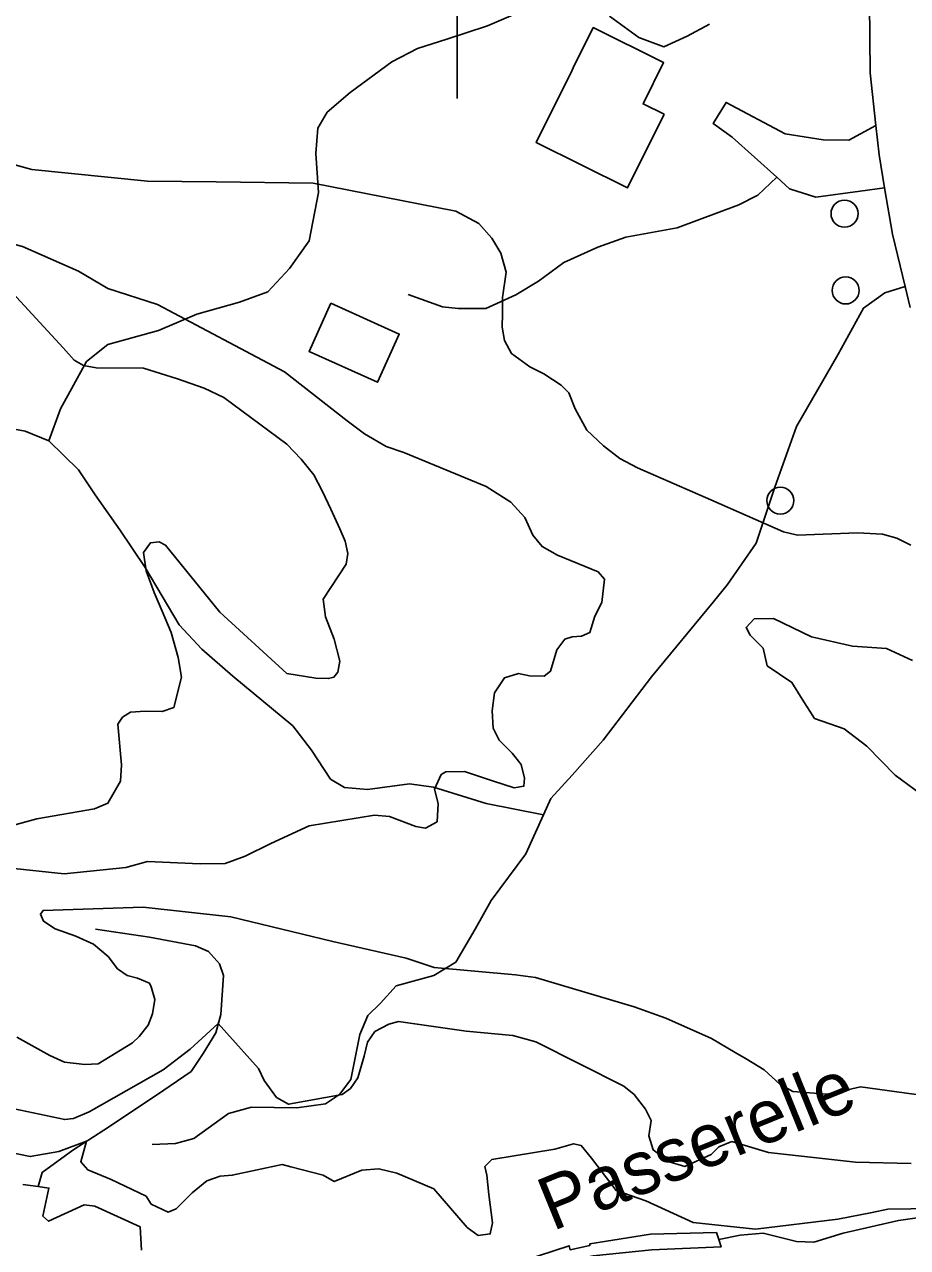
# Model space of a CAD drawing. Extents: x 362852 to 366875, y 5563573 to 5566479.
# Drawn here: x 363568 to 363633.3, y 5564105 to 5564195.5 of the extents above; entities that cross this region are included whole.
import ezdxf

# ---------------------------------------------------------------- set-up
doc = ezdxf.new("R2010")
doc.units = 0
for name, color, linetype in [('Niveau 1', 7, 'Continuous'), ('Niveau 19', 7, 'Continuous'), ('Niveau 2', 7, 'Continuous'), ('Niveau 21', 7, 'Continuous'), ('Niveau 22', 7, 'Continuous'), ('Niveau 26', 7, 'Continuous'), ('Niveau 31', 7, 'Continuous'), ('Niveau 36', 7, 'Continuous'), ('Niveau 4', 7, 'Continuous'), ('Niveau 61', 7, 'Continuous')]:
    doc.layers.add(name, color=color, linetype=linetype)

msp = doc.modelspace()

# ---------------------------------------------------------------- linework, layer by layer
at = {"layer": 'Niveau 1'}
msp.add_lwpolyline([(363566.31, 5564176.54), (363570.89, 5564171.56), (363571.71, 5564170.65), (363572.38, 5564170.25), (363573.32, 5564170.08), (363576.82, 5564170.06), (363579.34, 5564169.25), (363581.3, 5564168.58), (363582.77, 5564167.89), (363587.41, 5564164.42), (363588.49, 5564163.31), (363589.42, 5564162.15), (363590.06, 5564160.92), (363590.67, 5564159.62), (363591.34, 5564158.16), (363591.72, 5564157.26), (363591.92, 5564156.34), (363591.81, 5564155.55), (363590.1, 5564152.96), (363590.27, 5564151.66), (363590.91, 5564150), (363591.34, 5564148.38), (363591.18, 5564147.56), (363590.9, 5564147.19), (363590.51, 5564147.09), (363589.56, 5564147.13), (363587.42, 5564147.48), (363582.47, 5564152), (363578.45, 5564156.97), (363577.98, 5564157.21), (363577.33, 5564157.13), (363576.82, 5564156.41), (363577.01, 5564155.06), (363577.62, 5564153.45), (363578.2, 5564152.07), (363578.87, 5564150.49), (363579.39, 5564148.65), (363579.63, 5564147.19), (363579.07, 5564144.96), (363578.2, 5564144.66), (363576.94, 5564144.69), (363575.86, 5564144.61), (363575.27, 5564144.24), (363574.92, 5564143.72), (363575.19, 5564140.71), (363575.13, 5564139.51), (363574.2, 5564137.87), (363573.2, 5564137.45), (363568.95, 5564136.72), (363566.88, 5564136.16)], dxfattribs=at)
at = {"layer": 'Niveau 19'}
msp.add_lwpolyline([(363631.6, 5564183.39), (363629.8, 5564183.13), (363626.53, 5564182.7), (363624.58, 5564183.32), (363623.64, 5564184.17), (363620.33, 5564187.13), (363618.94, 5564188.14), (363619.88, 5564189.7), (363624.26, 5564187.38), (363627.07, 5564186.93), (363628.96, 5564186.91), (363630.96, 5564187.99)], dxfattribs=at)
at = {"layer": 'Niveau 2'}
for points in [[(363536.07, 5564212.57), (363538.28, 5564211.63), (363539.95, 5564210.64), (363541.47, 5564209.4), (363545.42, 5564205.94), (363548.14, 5564203.33), (363549.77, 5564201.39), (363551.22, 5564199.44), (363552.37, 5564197.73), (363553.17, 5564196.26), (363557.49, 5564188.95), (363559.34, 5564187.23), (363560.39, 5564186.98), (363561.65, 5564186.63), (363568.58, 5564184.73), (363577.12, 5564183.88), (363582.2, 5564183.83), (363589.37, 5564183.72), (363599.92, 5564181.66), (363601.62, 5564180.74), (363602.58, 5564179.65), (363603.23, 5564178.55), (363603.63, 5564177.15)], [(363524.9, 5564201.47), (363536.51, 5564194.18), (363547.07, 5564189.26), (363557.67, 5564183.92), (363560.63, 5564181.61), (363562.21, 5564180.83), (363563.68, 5564180.14), (363564.32, 5564179.97), (363567.89, 5564179.04), (363570.8, 5564177.77), (363572.02, 5564177.22), (363574.18, 5564175.94), (363577.86, 5564174.75), (363587.25, 5564169.77)], [(363603.63, 5564177.15), (363603.35, 5564175.28), (363603.35, 5564174.1), (363603.33, 5564173.09), (363603.5, 5564172.1), (363604.03, 5564171.13), (363605.38, 5564170.14), (363606.41, 5564169.63), (363607.7, 5564168.8), (363608.25, 5564168.22), (363608.74, 5564167.05), (363609.59, 5564165.47), (363610.83, 5564164.3), (363612.04, 5564163.37), (363613.33, 5564162.67), (363618.75, 5564160.32), (363624.12, 5564157.95), (363625.16, 5564157.7), (363629.59, 5564157.88), (363631.44, 5564157.78), (363632.51, 5564157.48), (363633.53, 5564156.97)], [(363587.25, 5564169.77), (363591.89, 5564166.16), (363593.16, 5564165.2), (363594.75, 5564164.25), (363596.06, 5564163.8), (363602.16, 5564161.31), (363603.97, 5564160.13), (363605, 5564159.01), (363605.61, 5564157.7), (363606.28, 5564156.86), (363607.42, 5564156.22), (363610.43, 5564154.99), (363610.91, 5564154.44), (363610.69, 5564152.73), (363610.19, 5564151.7), (363609.82, 5564150.49), (363609.19, 5564150.22), (363608.52, 5564150.19), (363607.96, 5564150.02), (363607.37, 5564149.21), (363606.9, 5564147.64), (363606.44, 5564147.26), (363605.36, 5564147.3), (363604.55, 5564147.46), (363603.5, 5564147.14), (363602.78, 5564146.03), (363602.59, 5564144.7), (363602.68, 5564143.43), (363603.12, 5564142.55), (363604.08, 5564141.59), (363604.75, 5564140.74), (363604.99, 5564139.72), (363604.93, 5564139.13), (363604.22, 5564139.02), (363602.63, 5564139.54), (363600.54, 5564140.22), (363599.17, 5564140.21), (363598.82, 5564140), (363598.34, 5564138.92), (363598.6, 5564137.85), (363598.54, 5564136.51), (363597.68, 5564136.03), (363596.95, 5564136.15), (363595.01, 5564136.9), (363593.91, 5564137), (363589.06, 5564136.21), (363586.24, 5564134.9), (363584.33, 5564133.97), (363582.87, 5564133.42), (363581.01, 5564133.39), (363577.13, 5564133.56), (363575.51, 5564133.13), (363570.96, 5564132.66), (363566.79, 5564133.09)], [(363634.26, 5564138.58), (363632.37, 5564139.96), (363630.29, 5564142.09), (363628.62, 5564143.38), (363626.43, 5564144.15), (363625.52, 5564145.57), (363624.75, 5564146.81), (363622.92, 5564148.04), (363622.62, 5564149.35), (363621.66, 5564150.31), (363621.36, 5564150.88), (363621.97, 5564151.51), (363623.39, 5564151.54), (363626.21, 5564150.17), (363629.23, 5564149.5), (363631.75, 5564149.31), (363633.67, 5564148.44)], [(363635.18, 5564116.16), (363629.81, 5564116.9), (363628.55, 5564116.62), (363627.34, 5564116.37), (363624.83, 5564116.56), (363623.85, 5564117.09), (363622.71, 5564118.17), (363621.37, 5564118.98), (363620.55, 5564119.45), (363618.81, 5564120.47), (363615.43, 5564121.98), (363613.08, 5564122.81), (363605.79, 5564124.99), (363604.33, 5564125.19), (363598.3, 5564125.72), (363596.25, 5564126.42), (363590.81, 5564127.64), (363583.29, 5564129.47), (363576.8, 5564130.19), (363569.4, 5564129.95), (363569.21, 5564129.68), (363569.43, 5564129.15), (363570.29, 5564128.58), (363571.83, 5564128.04), (363573.14, 5564127.46), (363574.21, 5564126.54), (363574.9, 5564125.64), (363575.62, 5564125.13), (363576.38, 5564124.95), (363577.28, 5564124.58)], [(363580.27, 5564119.69), (363578.28, 5564118.17), (363572.82, 5564115.06), (363571.65, 5564114.57), (363571, 5564114.48), (363566.33, 5564115.47), (363562.24, 5564117.31), (363561.74, 5564117.92), (363560.98, 5564118.97), (363560.19, 5564119.52), (363558.96, 5564120.06), (363557.14, 5564120.37), (363551.49, 5564120.12), (363550.1, 5564119.85), (363548.81, 5564119.93), (363547.81, 5564120.39), (363546.88, 5564121.25), (363543.51, 5564124.65)], [(363577.28, 5564124.58), (363577.4, 5564124.31), (363577.67, 5564123.36), (363577.5, 5564122.29), (363577.16, 5564121.46), (363576.51, 5564120.62), (363576.01, 5564120.17), (363573.48, 5564118.6), (363572.5, 5564118.56), (363570.99, 5564118.74), (363569.91, 5564119.23), (363567.47, 5564120.58)], [(363600.68, 5564121.01), (363595.68, 5564121.73), (363594.95, 5564121.54), (363593.93, 5564120.99), (363593.38, 5564120.2), (363593.13, 5564119.16), (363592.67, 5564117.58), (363592.13, 5564116.79), (363591.5, 5564116.34), (363587.55, 5564115.62), (363586.65, 5564116.12), (363585.75, 5564117.37), (363585.32, 5564118.25), (363582.35, 5564121.58), (363580.27, 5564119.69)], [(363633.57, 5564111.24), (363629.46, 5564111.33), (363623.02, 5564112.06), (363620.31, 5564112.86), (363619.35, 5564112.46), (363618.77, 5564111.9), (363616.83, 5564111.02), (363615.68, 5564111.36), (363614.5, 5564112.24), (363614.18, 5564113.29), (363614.34, 5564114.42), (363613.92, 5564115.25), (363613.09, 5564116.34), (363612.33, 5564116.96), (363605.82, 5564120.23), (363604.12, 5564120.71), (363600.68, 5564121.01)], [(363565.44, 5564112.36), (363568.46, 5564111.74), (363570.56, 5564112.12), (363572.62, 5564112.88), (363572.19, 5564111.37), (363572.7, 5564110.77), (363574.44, 5564110.05), (363577.02, 5564108.82), (363577.4, 5564108.23), (363578.65, 5564107.63), (363579.24, 5564107.87), (363580.43, 5564109.06), (363581.5, 5564109.95), (363582.48, 5564110.3), (363583.39, 5564110.37), (363587.07, 5564111.16), (363587.71, 5564110.99), (363590.1, 5564110.37), (363590.92, 5564109.9), (363592.95, 5564110.75), (363594.22, 5564110.85), (363595.55, 5564110.53), (363598.29, 5564109.36), (363600.75, 5564106.51), (363601.56, 5564105.91), (363602.45, 5564106.03), (363602.61, 5564106.85), (363602.36, 5564108.94), (363602.19, 5564110.37), (363602.05, 5564111.01), (363602.58, 5564111.54), (363607.22, 5564112.3), (363608.61, 5564112.7), (363609.18, 5564112.56), (363609.94, 5564111.62), (363611.75, 5564109.25), (363613.96, 5564108.48), (363617.45, 5564106.88), (363622.05, 5564106.37)], [(363622.05, 5564106.37), (363628.14, 5564107.11), (363630.68, 5564107.61), (363631.84, 5564107.85), (363636.94, 5564107.93), (363638.85, 5564107.87), (363638.82, 5564105.83), (363639.35, 5564104.43)]]:
    msp.add_lwpolyline(points, dxfattribs=at)
at = {"layer": 'Niveau 21'}
msp.add_lwpolyline([(363630.48, 5564197.07), (363630.54, 5564191.9), (363630.96, 5564187.99), (363631.19, 5564185.83), (363631.6, 5564183.39), (363632.18, 5564179.96), (363633.11, 5564176.08), (363633.49, 5564174.54)], dxfattribs=at)
at = {"layer": 'Niveau 22'}
for points in [[(363569.83, 5564164.68), (363570.7, 5564167.04), (363572.6, 5564170.54), (363574.2, 5564171.8), (363577.93, 5564172.84), (363580.77, 5564174.03), (363583.91, 5564174.94), (363586.02, 5564175.7), (363587.61, 5564177.43), (363589.08, 5564179.46), (363589.76, 5564183.03), (363589.56, 5564185.92), (363589.7, 5564187.8), (363590.39, 5564188.97), (363592.09, 5564190.43), (363595.19, 5564192.69), (363597.08, 5564193.68), (363599.24, 5564194.38), (363602.24, 5564195.36), (363604.5, 5564196.33)], [(363611.26, 5564196.08), (363613.43, 5564194.49), (363615.28, 5564193.82), (363617.01, 5564194.61), (363618.65, 5564195.48)], [(363596.39, 5564175.49), (363598.92, 5564174.59), (363600.09, 5564174.46), (363602.12, 5564174.47), (363604.35, 5564175.48), (363606.01, 5564176.47), (363607.89, 5564177.86), (363610.41, 5564178.99), (363612.48, 5564179.73), (363616.26, 5564180.43), (363620.83, 5564182.13), (363622.22, 5564182.84), (363623.64, 5564184.17)], [(363577.46, 5564112.64), (363579.2, 5564112.71), (363580.55, 5564113.09), (363583.11, 5564114.92), (363584.81, 5564115.39), (363588.16, 5564115.36), (363590.27, 5564115.65), (363591.3, 5564116.33), (363592.15, 5564117.44), (363592.81, 5564120.78), (363593.41, 5564122.17), (363594.34, 5564123.09), (363595.51, 5564124.37), (363598.29, 5564125.13), (363599.92, 5564126.13), (363601.35, 5564128.57), (363602.53, 5564130.69), (363605.09, 5564134.14), (363606.39, 5564137.03), (363606.92, 5564138.22), (363608.51, 5564139.95), (363610.8, 5564142.54), (363614.38, 5564147.23), (363618.94, 5564152.74), (363620, 5564154.06), (363622.11, 5564157.11), (363623.48, 5564161.25), (363625.08, 5564165.74), (363628.15, 5564171.04), (363630.04, 5564174.49), (363631.63, 5564175.61), (363633.11, 5564176.08)], [(363606.39, 5564137.03), (363602.14, 5564137.86), (363598.26, 5564139.06), (363596.49, 5564139.32), (363593.38, 5564138.88), (363591.69, 5564139.05), (363590.64, 5564139.66), (363589.25, 5564141.79), (363587.86, 5564143.6), (363583.42, 5564147.28), (363581.14, 5564149.27), (363579.47, 5564151.06), (363576.96, 5564155.3), (363575.08, 5564158.09), (363573.26, 5564160.68), (363572.01, 5564162.52), (363569.83, 5564164.68), (363568.09, 5564165.4), (363562, 5564166.52)], [(363673.76, 5564121.07), (363671.87, 5564119.9), (363669.47, 5564118.34), (363666.02, 5564115.4), (363661.52, 5564111.82), (363656.4, 5564109.32), (363653.43, 5564108.29), (363651.62, 5564107.87), (363648.49, 5564107.54), (363645.34, 5564107.5), (363640.59, 5564108.01), (363637.93, 5564107.79), (363632.63, 5564107.02), (363628.53, 5564106.09), (363626.37, 5564105.42), (363625.1, 5564105.46), (363622.62, 5564106.08), (363620.93, 5564105.94), (363619.35, 5564105.61)]]:
    msp.add_lwpolyline(points, dxfattribs=at)
at = {"layer": 'Niveau 26'}
msp.add_lwpolyline([(363619.17, 5564106.14), (363619.35, 5564105.61), (363619.52, 5564105.07), (363614.39, 5564104.84), (363610.07, 5564104.4), (363608.52, 5564104.08), (363608.5, 5564103.83), (363604.79, 5564102.76), (363603.91, 5564102.57), (363603.57, 5564102.5), (363603.69, 5564103.65), (363608.29, 5564105.15), (363608.35, 5564104.86), (363609.81, 5564105.17), (363609.82, 5564105.3), (363614.29, 5564106.02), (363619.17, 5564106.14)], dxfattribs=at)
at = {"layer": 'Niveau 31'}
for points in [[(363615.3, 5564188.82), (363612.6, 5564183.38), (363605.85, 5564186.73), (363608.5, 5564192.08), (363608.59, 5564192.26), (363610.07, 5564195.23), (363615.27, 5564192.65), (363613.75, 5564189.59), (363615.3, 5564188.82)], [(363590.66, 5564174.86), (363595.73, 5564172.57), (363594.13, 5564169.01), (363589.06, 5564171.29), (363590.66, 5564174.86)]]:
    msp.add_lwpolyline(points, dxfattribs=at)
at = {"layer": 'Niveau 36'}
for centre in [(363628.641, 5564181.475), (363628.722, 5564175.797), (363623.895, 5564160.255)]:
    msp.add_circle(centre, 1, dxfattribs=at)
at = {"layer": 'Niveau 4'}
for points in [[(363573.27, 5564128.56), (363577.28, 5564127.96), (363580.68, 5564127.33), (363581.64, 5564126.92), (363582.45, 5564126.01), (363582.75, 5564125.14), (363582.53, 5564122.26), (363582.17, 5564120.89), (363581.24, 5564119.37), (363580.34, 5564118.05), (363577.78, 5564116.29), (363573.89, 5564113.71), (363571.6, 5564112.21), (363569.34, 5564110.57), (363569.03, 5564109.53)], [(363567.91, 5564109.68), (363569.03, 5564109.53), (363569.84, 5564109.42), (363569.39, 5564107.35), (363569.81, 5564106.96), (363572.43, 5564108.19), (363573.23, 5564108.08), (363576.58, 5564106.54), (363576.68, 5564104.82)]]:
    msp.add_lwpolyline(points, dxfattribs=at)
at = {"layer": 'Niveau 61'}
msp.add_line((363600, 5564210), (363600, 5564190), dxfattribs=at)

# ---------------------------------------------------------------- texts
at = {"layer": 'Niveau 26'}
msp.add_text('Passerelle', height=3.93, rotation=22.09, dxfattribs=at).set_placement((363607.05, 5564106.21))

doc.saveas('drawing.dxf')
